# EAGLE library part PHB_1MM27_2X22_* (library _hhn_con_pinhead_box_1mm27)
Pin Header Box-Type, 1.27mm/0.5"/50mil Pitch, 2x22 Circuits Note: see library description for an important note about THT-version
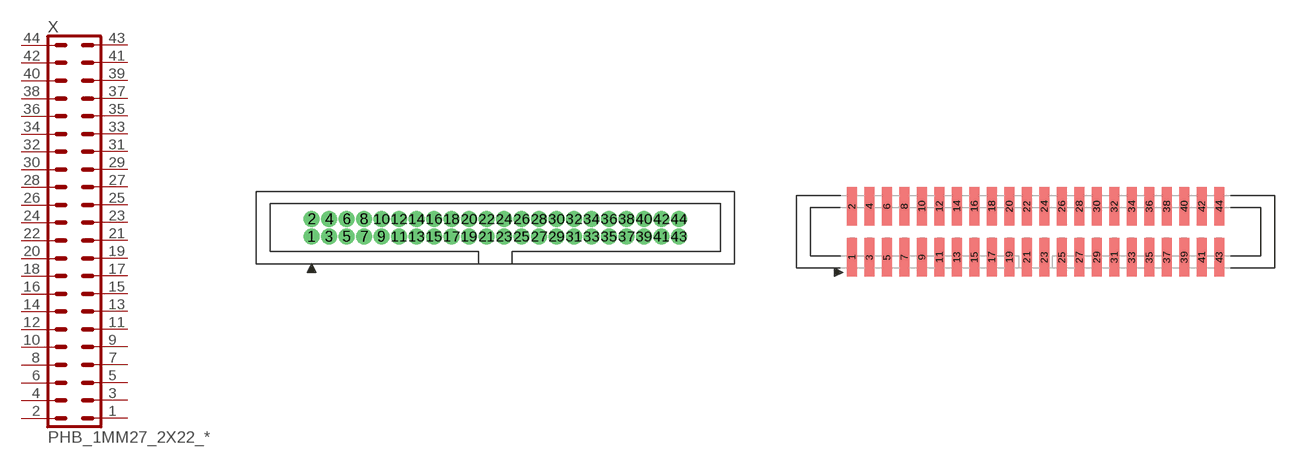
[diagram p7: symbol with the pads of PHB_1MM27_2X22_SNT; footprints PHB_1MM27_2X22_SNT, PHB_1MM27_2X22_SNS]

Designator prefix X

## PHB_1MM27_2X22_SNT  [PHB_1MM27_2X22_SNT]
1  1  pas
2  2  pas
3  3  pas
4  4  pas
5  5  pas
6  6  pas
7  7  pas
8  8  pas
9  9  pas
10  10  pas
11  11  pas
12  12  pas
13  13  pas
14  14  pas
15  15  pas
16  16  pas
17  17  pas
18  18  pas
19  19  pas
20  20  pas
21  21  pas
22  22  pas
23  23  pas
24  24  pas
25  25  pas
26  26  pas
27  27  pas
28  28  pas
29  29  pas
30  30  pas
31  31  pas
32  32  pas
33  33  pas
34  34  pas
35  35  pas
36  36  pas
37  37  pas
38  38  pas
39  39  pas
40  40  pas
41  41  pas
42  42  pas
43  43  pas
44  44  pas

## PHB_1MM27_2X22_SNS  [PHB_1MM27_2X22_SNS]
Pads as for PHB_1MM27_2X22_SNT

## Footprint PHB_1MM27_2X22_SNT (pad centres in mm)
Pin Header Box-Type, 1.27mm Pitch, 2x22 circuits, Straight, No Locking, THT Important Note: Diameter in this lbr is set to a specific value (NOT 'auto' = 0), this is ignored by actual eagle versions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
drill 0.65 pad 1 round: 1 -13.335,-0.635; 2 -13.335,0.635; 3 -12.065,-0.635; 4 -12.065,0.635; 5 -10.795,-0.635; 6 -10.795,0.635; 7 -9.525,-0.635; 8 -9.525,0.635; 9 -8.255,-0.635; 10 -8.255,0.635; 11 -6.985,-0.635; 12 -6.985,0.635; 13 -5.715,-0.635; 14 -5.715,0.635; 15 -4.445,-0.635; 16 -4.445,0.635; 17 -3.175,-0.635; 18 -3.175,0.635; 19 -1.905,-0.635; 20 -1.905,0.635; 21 -0.635,-0.635; 22 -0.635,0.635; 23 0.635,-0.635; 24 0.635,0.635; 25 1.905,-0.635; 26 1.905,0.635; 27 3.175,-0.635; 28 3.175,0.635; 29 4.445,-0.635; 30 4.445,0.635; 31 5.715,-0.635; 32 5.715,0.635; 33 6.985,-0.635; 34 6.985,0.635; 35 8.255,-0.635; 36 8.255,0.635; 37 9.525,-0.635; 38 9.525,0.635; 39 10.795,-0.635; 40 10.795,0.635; 41 12.065,-0.635; 42 12.065,0.635; 43 13.335,-0.635; 44 13.335,0.635

## Footprint PHB_1MM27_2X22_SNS (pad centres in mm)
Pin Header Box-Type, 1.27mm Pitch, 2x22 circuits, Straight, No Locking, SMT
smd 0.76 x 2.8: 1 -13.335,-1.85; 2 -13.335,1.85; 3 -12.065,-1.85; 4 -12.065,1.85; 5 -10.795,-1.85; 6 -10.795,1.85; 7 -9.525,-1.85; 8 -9.525,1.85; 9 -8.255,-1.85; 10 -8.255,1.85; 11 -6.985,-1.85; 12 -6.985,1.85; 13 -5.715,-1.85; 14 -5.715,1.85; 15 -4.445,-1.85; 16 -4.445,1.85; 17 -3.175,-1.85; 18 -3.175,1.85; 19 -1.905,-1.85; 20 -1.905,1.85; 21 -0.635,-1.85; 22 -0.635,1.85; 23 0.635,-1.85; 24 0.635,1.85; 25 1.905,-1.85; 26 1.905,1.85; 27 3.175,-1.85; 28 3.175,1.85; 29 4.445,-1.85; 30 4.445,1.85; 31 5.715,-1.85; 32 5.715,1.85; 33 6.985,-1.85; 34 6.985,1.85; 35 8.255,-1.85; 36 8.255,1.85; 37 9.525,-1.85; 38 9.525,1.85; 39 10.795,-1.85; 40 10.795,1.85; 41 12.065,-1.85; 42 12.065,1.85; 43 13.335,-1.85; 44 13.335,1.85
